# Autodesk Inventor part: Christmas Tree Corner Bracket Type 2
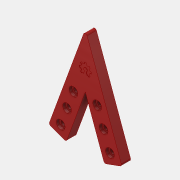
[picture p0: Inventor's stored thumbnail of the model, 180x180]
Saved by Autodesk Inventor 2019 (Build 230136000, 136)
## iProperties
Created: 2025-12
Part Number: Christmas Tree Corner Bracket Type 2
Material: ABS Plastic
Document SubType Name: Modeling
Designer: sab
Mass: 34.6917 g
Surface Area: 118.906 cm^2
Volume: 32.728 cm^3
Density: 1.06 g/cm^3
Appearance: Red
Author: sab
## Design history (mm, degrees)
node "Blocks"
  sketch "Block1"
    geometry: L1 (0, 0.5)-(342.02, 940.193); L2 (0, -4.92)-(0, 0); L3 (0, -19.5)-(684.04, -19.5); L4 (21.284, 0.5)-(342.02, 881.717); L5 (0, 0.5)-(684.04, 0.5); L6 (662.757, 0.5)-(342.02, 881.717); L7 (684.04, 0.5)-(342.02, 940.193); L8 (684.04, -4.92)-(684.04, 0); L9 (0, 0.5)-(0, 0); L10 (684.04, 0.5)-(684.04, 0); 1 further point
    constraints: 20 end point
  sketch "Block1_1"
    geometry: L1 (-5.09, 2.943)-(-3.464, 3.257); L2 (-3.464, 3.257)-(-2.886, 4.652); L3 (-2.886, 4.652)-(-3.839, 6.061); L4 (-3.839, 6.061)-(-2.636, 7.264); L5 (-2.636, 7.264)-(-1.238, 6.318); L6 (-1.238, 6.318)-(0.22, 6.922); L7 (0.22, 6.922)-(0.531, 8.532); L8 (0.531, 8.532)-(2.267, 8.532); L9 (2.267, 8.532)-(2.588, 6.869); L10 (2.588, 6.869)-(4.046, 6.265); L11 (4.046, 6.265)-(5.403, 7.184); L12 (5.403, 7.184)-(6.631, 5.956); L13 (6.631, 5.956)-(5.682, 4.554); L14 (5.682, 4.554)-(6.286, 3.096); L15 (6.286, 3.096)-(7.895, 2.785); L16 (7.895, 2.785)-(7.895, 1.05); L17 (7.895, 1.05)-(6.232, 0.729); L18 (6.232, 0.729)-(5.627, -0.731); L19 (5.627, -0.731)-(6.541, -2.081); L20 (6.541, -2.081)-(5.344, -3.279); L21 (5.344, -3.279)-(3.887, -2.293); L22 (3.887, -2.293)-(3.329, -2.524); L23 (3.329, -2.524)-(2.197, 0.247); L24 (0.657, 0.303)-(-0.496, -2.521); L25 (-0.496, -2.521)-(-1.178, -2.239); L26 (-1.178, -2.239)-(-2.536, -3.157); L27 (-2.536, -3.157)-(-3.766, -1.927); L28 (-3.766, -1.927)-(-2.82, -0.529); L29 (-2.82, -0.529)-(-3.42, 0.919); L30 (-3.42, 0.919)-(-5.09, 1.242); L31 (-5.09, 1.242)-(-5.09, 2.943); A1 r 0.085 centre (-3.45, 3.333) between (-3.434, 3.25) and (-3.371, 3.301); A2 r 0.085 centre (-2.899, 4.663) between (-2.82, 4.63) and (-2.828, 4.711); A3 r 0.085 centre (-3.663, 6.098) between (-3.724, 6.158) and (-3.734, 6.05); A4 r 0.085 centre (-2.519, 7.242) between (-2.471, 7.312) and (-2.58, 7.302); A5 r 0.085 centre (-1.085, 6.477) between (-1.132, 6.407) and (-1.052, 6.398); A6 r 0.085 centre (0.245, 7.028) between (0.278, 6.949) and (0.329, 7.012); A7 r 0.085 centre (0.719, 8.583) between (0.719, 8.668) and (0.635, 8.599); A8 r 0.085 centre (2.337, 8.583) between (2.421, 8.599) and (2.337, 8.668); A9 r 0.085 centre (2.811, 7.028) between (2.727, 7.012) and (2.778, 6.949); A10 r 0.085 centre (4.14, 6.477) between (4.108, 6.398) and (4.188, 6.407); A11 r 0.085 centre (5.575, 7.242) between (5.636, 7.302) and (5.527, 7.312); A12 r 0.085 centre (6.719, 6.098) between (6.79, 6.05) and (6.78, 6.158); A13 r 0.085 centre (5.955, 4.663) between (5.884, 4.711) and (5.876, 4.63); A14 r 0.085 centre (6.506, 3.333) between (6.427, 3.301) and (6.489, 3.25); A15 r 0.085 centre (8.06, 2.859) between (8.146, 2.859) and (8.077, 2.943); A16 r 0.085 centre (8.06, 1.242) between (8.077, 1.158) and (8.146, 1.242); A17 r 0.085 centre (6.506, 0.768) between (6.489, 0.851) and (6.427, 0.8); A18 r 0.085 centre (5.955, -0.562) between (5.876, -0.529) and (5.884, -0.61); A19 r 0.085 centre (6.719, -1.997) between (6.78, -2.057) and (6.79, -1.949); A20 r 0.085 centre (5.575, -3.141) between (5.527, -3.212) and (5.636, -3.201); A21 r 0.085 centre (4.14, -2.376) between (4.188, -2.306) and (4.108, -2.297); A22 r 0.085 centre (3.466, -2.471) between (3.387, -2.503) and (3.499, -2.55); A23 r 0.085 centre (2.345, 0.274) between (2.31, 0.352) and (2.266, 0.242); A24 r 1.87 centre (1.489, 1.977) between (2.197, 0.247) and (0.657, 0.303); A25 r 0.085 centre (0.71, 0.274) between (0.79, 0.242) and (0.746, 0.352); A26 r 0.085 centre (-0.41, -2.471) between (-0.443, -2.55) and (-0.331, -2.503); A27 r 0.085 centre (-1.085, -2.376) between (-1.052, -2.297) and (-1.132, -2.306); A28 r 0.085 centre (-2.519, -3.141) between (-2.58, -3.201) and (-2.471, -3.212); A29 r 0.085 centre (-3.663, -1.997) between (-3.734, -1.949) and (-3.724, -2.057); A30 r 0.085 centre (-2.899, -0.562) between (-2.828, -0.61) and (-2.82, -0.529); A31 r 0.085 centre (-3.45, 0.768) between (-3.371, 0.8) and (-3.434, 0.851); A32 r 0.085 centre (-5.005, 1.242) between (-5.09, 1.242) and (-5.021, 1.158); A33 r 0.085 centre (-5.005, 2.859) between (-5.021, 2.943) and (-5.09, 2.859); 1 further point
    constraints: 66 point on circle, 62 end point, 33 centre point
sketch "Sketch1"
  geometry: L1 (0, 0)-(-20.521, -56.382); L2 (-20.521, -56.382)-(-39.315, -49.541); L3 (-39.315, -49.541)-(0, 58.476); L4 (-18.794, 6.84)-(0, 0); L5 (0, 0)-(20.521, -56.382); L6 (20.521, -56.382)-(39.315, -49.541) reference; L7 (39.315, -49.541)-(0, 58.476); L8 (18.794, 6.84)-(0, 0); L9 (-29.918, -52.961)-(5.321, 43.857); L10 (-29.918, -52.961)-(73.114, -52.961); L11 (29.918, -52.961)-(-5.321, 43.857); L12 (29.918, -52.961)-(132.95, -52.961); 7 further points
  constraints: 24 end point, 11 point on line, 4 parallel, 2 equal length, 2 horizontal, 2 perpendicular, 1 midpoint, 6 other
  dimensions: "d0" = 60 distance of L1.start L1.end; "d1" = 70 deg angle of L10 L9; "d2" = 110 deg angle of L12 L11; "d3" = 10 distance from line of L2 point (-26.498, -43.564); "d4" = 30 distance from line of point (-19.658, -24.771) L2; "d5" = 50 distance from line of point (-12.817, -5.977) L2; "d6" = 30 distance from line of point (19.658, -24.771) L6 (= d4); "d7" = 50 distance from line of point (12.817, -5.977) L6 (= d5)
  node "Block1:1" dims "d0" = 60, "d1" = 70 deg, "d2" = 110 deg, "d3" = 10, "d4" = 30, "d5" = 50, "d6" = 30 (= d4), "d7" = 50 (= d5)
  node "Block1_1:1"
extrude "Extrusion1" new body sketch "Sketch1" distance "d8" = 10; taper "d9" = 0 deg
hole "Hole1" sketch "Sketch1" diameter "d10" = 5.4; stored, may be unused: countersink angle "d14" = 90 deg, drill point angle "d16" = 118 deg; dims "d11" = 6, "d12" = 9.5, "d13" = 3, "d15" = 8
emboss "Emboss1" sketch "Sketch1" dims "d7" = 50 (= d5), "d17" = 0.3, "d18" = 0
fillet "Fillet1" dims "d19" = 2
body "Solid1"
